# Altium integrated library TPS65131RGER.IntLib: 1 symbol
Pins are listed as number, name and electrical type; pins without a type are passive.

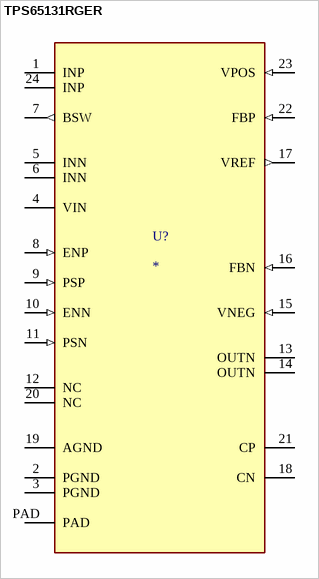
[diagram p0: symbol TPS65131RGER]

## TPS65131RGER
designator U?
Split-Rail Converter with Dual, Positive and Negative Outputs (750mA typ); MF: Texas Instruments; MP: TPS65131RGER
footprint RGE0024B
pins: 1 INP (power), 2 PGND (power), 3 PGND (power), 4 VIN (power), 5 INN (power), 6 INN (power), 7 BSW (out), 8 ENP (in), 9 PSP (in), 10 ENN (in), 11 PSN (in), 12 NC, 13 OUTN (power), 14 OUTN (power), 15 VNEG (in), 16 FBN (in), 17 VREF (out), 18 CN, 19 AGND (power), 20 NC, 21 CP, 22 FBP (in), 23 VPOS (in), 24 INP (power), PAD (power)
